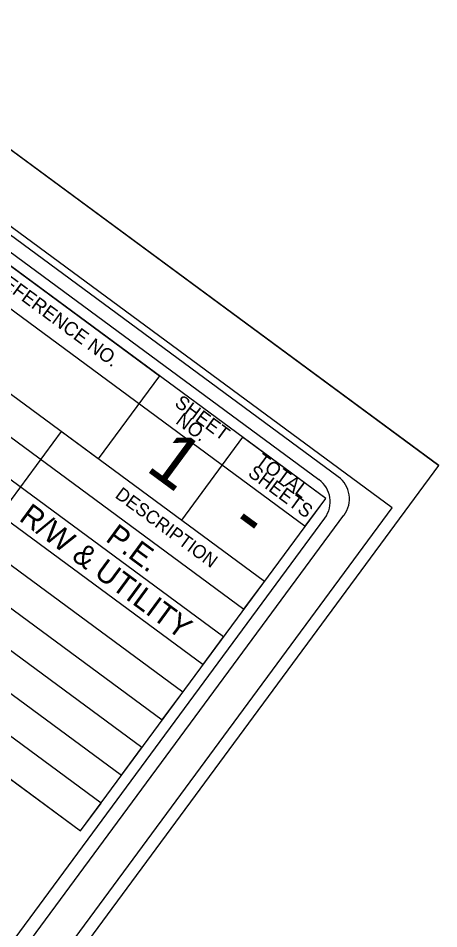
# Model space of a CAD drawing. Extents: x 945666 to 965748, y 644452 to 663300.
# Drawn here: x 964220 to 965748, y 651622 to 654930 of the extents above; entities that cross this region are included whole.
import ezdxf

# ---------------------------------------------------------------- set-up
doc = ezdxf.new("R2010")
doc.units = 0
for name, color, linetype in [('Sheet Cutting Line CELL', 7, 'Continuous'), ('Sheet Data Field CELL', 7, 'Continuous'), ('Sheet Plot Border Inside CELL', 7, 'Continuous'), ('Sheet Plot Border Outside CELL', 7, 'Continuous'), ('Sheet Title CELL', 7, 'Continuous')]:
    doc.layers.add(name, color=color, linetype=linetype)

msp = doc.modelspace()

# ---------------------------------------------------------------- linework, layer by layer
at = {"layer": 'Sheet Cutting Line CELL'}
msp.add_line((952195, 663300.2), (965747.9, 653304.9), dxfattribs=at)
at = {"layer": 'Sheet Plot Border Inside CELL'}
msp.add_lwpolyline([(945903.9, 654551), (959315.9, 644659.5), (965578.4, 653150.9), (952166.4, 663042.4)], close=True, dxfattribs=at)
at = {"layer": 'Sheet Plot Border Outside CELL'}
msp.add_lwpolyline([(965747.9, 653304.9), (952195, 663300.2), (945666.1, 654447.6), (959218.9, 644452.2)], close=True, dxfattribs=at)
at = {"layer": 'Sheet Title CELL'}
for points in [[(965382.3, 653263.9), (953471.1, 662048.6)], [(965312.3, 653253.4), (953884.2, 661681.7)], [(963049.5, 654717.3), (965262.7, 653085.1), (965336.9, 653185.7), (963123.6, 654817.8)], [(963425.5, 654595.4), (964733.3, 653630.7), (964510.7, 653329.1), (964376.3, 653428.2), (963708.5, 652522.8), (964446.5, 651978.5), (965336.9, 653185.7), (965035.1, 653408.3), (964812.6, 653106.4)], [(962826.8, 654415.4), (965040, 652783.2), (965114.3, 652883.9), (962901.1, 654516.2)], [(962678.4, 654214.2), (964891.7, 652582.1), (964965.8, 652682.6), (962752.6, 654314.8)], [(962530.1, 654013.2), (964743.3, 652380.9), (964817.5, 652481.5), (962604.3, 654113.8)], [(962381.7, 653811.9), (964594.9, 652179.6), (964669.1, 652280.2), (962456, 653912.4)], [(962233.4, 653610.8), (964446.5, 651978.5), (964520.7, 652079), (962307.5, 653711.4)], [(959289.8, 644834.8), (965403.3, 653124.1)], [(960377.3, 646393.5), (965333.4, 653113.7)]]:
    msp.add_lwpolyline(points, dxfattribs=at)
for centre in [(965253.3, 653173.4), (965323.2, 653183.9)]:
    msp.add_arc(centre, 100, 323.5908, 53.5908, dxfattribs=at)

# ---------------------------------------------------------------- texts
at = {"layer": 'Sheet Data Field CELL'}
for s, p in [('R/W & UTILITY', (964219.1, 653107.7)), ('P.E.', (964533.4, 653033.4))]:
    msp.add_text(s, height=80, rotation=323.5908, dxfattribs=at).set_placement(p)
at = {"layer": 'Sheet Title CELL'}
for s, height, p in [('STATE PROJECT REFERENCE NO.', 49.998, (963665.9, 654321.6)), ('SHEET', 50, (964784.7, 653524.5)), ('NO.', 50, (964788.7, 653460.1)), ('1', 193.5, (964678.9, 653290.1)), ('TOTAL', 50, (965078.1, 653312.5)), ('SHEETS', 50, (965051.2, 653270.3)), ('DESCRIPTION', 48, (964568.6, 653191.1)), ('-', 193.5, (964979, 653068.8))]:
    msp.add_text(s, height=height, rotation=323.5908, dxfattribs=at).set_placement(p)

doc.saveas('drawing.dxf')
